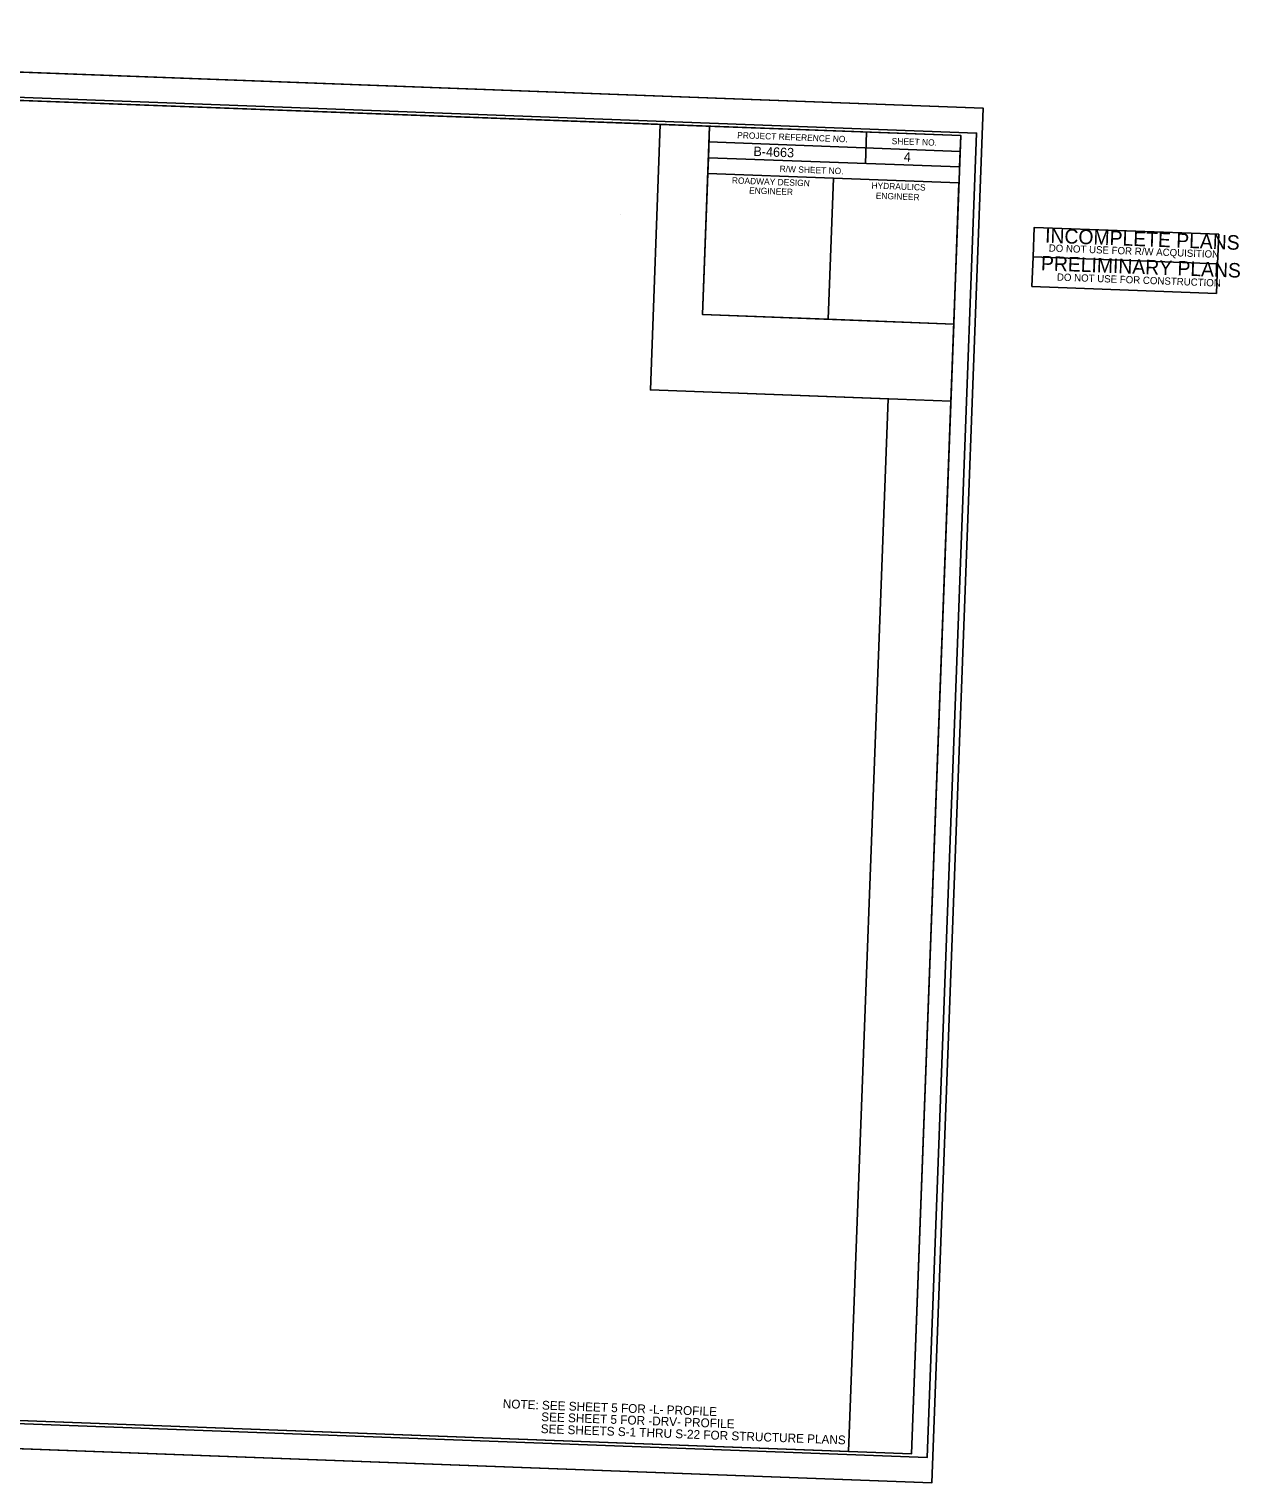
# Model space of a CAD drawing. Extents: x 2170073 to 2172001, y 723518 to 724675.
# Drawn here: x 2171037 to 2172001, y 723518 to 724675 of the extents above; entities that cross this region are included whole.
import ezdxf

# ---------------------------------------------------------------- set-up
doc = ezdxf.new("R2010")
doc.units = 0
for name, color, linetype in [('Prop Dimension Text', 7, 'Continuous'), ('Sheet Clip Boundary CELL', 7, 'Continuous'), ('Sheet Cutting Line CELL', 7, 'Continuous'), ('Sheet Data Field CELL', 7, 'Continuous'), ('Sheet North Arrow Point CELL', 7, 'Continuous'), ('Sheet Plan CELL', 7, 'Continuous'), ('Sheet Plan Layout CELL', 7, 'Continuous'), ('Sheet Plot Border Inside CELL', 7, 'Continuous'), ('Sheet Plot Border Outside CELL', 7, 'Continuous'), ('Sheet Sticker Incomplete CELL', 7, 'Continuous'), ('Sheet Sticker Preliminary CELL', 7, 'Continuous')]:
    doc.layers.add(name, color=color, linetype=linetype)

msp = doc.modelspace()

# ---------------------------------------------------------------- linework, layer by layer
at = {"layer": 'Sheet Clip Boundary CELL'}
msp.add_lwpolyline([(2170290.1, 723595.5), (2171689.1, 723543.2), (2171720.5, 724381.1), (2171531.3, 724388.2), (2171539.2, 724599.5), (2170329.3, 724644.8)], close=True, dxfattribs=at)
at = {"layer": 'Sheet Cutting Line CELL'}
for p, q in [((2171796.2, 724612.4), (2170113.8, 724675.4)), ((2170072.9, 723581.1), (2171755.2, 723518.2))]:
    msp.add_line(p, q, dxfattribs=at)
at = {"layer": 'Sheet North Arrow Point CELL'}
msp.add_line((2171507.7, 724527.7), (2171507.7, 724527.7), dxfattribs=at)
at = {"layer": 'Sheet Plan CELL'}
for p, q in [((2171703.3, 724593.3), (2171702.5, 724568.3)), ((2171577.9, 724585.5), (2171777.8, 724578)), ((2171577.5, 724573), (2171577, 724560.5)), ((2171577.5, 724573), (2171777.4, 724565.6)), ((2171577.5, 724573), (2171777.4, 724565.6)), ((2171677, 724556.8), (2171672.8, 724444.4))]:
    msp.add_line(p, q, dxfattribs=at)
for points in [[(2171778.4, 724590.6), (2170279.4, 724646.7), (2170240.1, 723597.4), (2171739.1, 723541.3)], [(2170240.1, 723597.4), (2170279.3, 724646.6), (2171578.4, 724598.1), (2171572.8, 724448.1), (2171772.7, 724440.6), (2171739.1, 723541.3)], [(2171578.4, 724598.1), (2171778.4, 724590.6), (2171777.4, 724565.6), (2171577.5, 724573)], [(2171577, 724560.5), (2171677, 724556.8), (2171672.8, 724444.4), (2171572.8, 724448.1)], [(2171677, 724556.8), (2171776.9, 724553.1), (2171772.7, 724440.6), (2171672.8, 724444.4)]]:
    msp.add_lwpolyline(points, close=True, dxfattribs=at)
at = {"layer": 'Sheet Plan Layout CELL'}
for points in [[(2170279.3, 724646.6), (2170240.1, 723597.4), (2171739.1, 723541.3), (2171770.4, 724379.2), (2171531.3, 724388.2), (2171539.2, 724599.5)], [(2171531.3, 724388.2), (2171770.4, 724379.2), (2171778.4, 724590.6), (2171539.2, 724599.5)]]:
    msp.add_lwpolyline(points, close=True, dxfattribs=at)
at = {"layer": 'Sheet Plot Border Inside CELL'}
msp.add_lwpolyline([(2170086.6, 723600.6), (2171751.5, 723538.4), (2171790.9, 724592.6), (2170126.1, 724654.9)], close=True, dxfattribs=at)
at = {"layer": 'Sheet Plot Border Outside CELL'}
msp.add_lwpolyline([(2170072.9, 723581.1), (2171755.2, 723518.2), (2171796.2, 724612.4), (2170113.8, 724675.4)], close=True, dxfattribs=at)
at = {"layer": 'Sheet Sticker Incomplete CELL'}
msp.add_lwpolyline([(2171835.9, 724494), (2171836.8, 724517.5), (2171983.7, 724512), (2171982.8, 724488.5)], close=True, dxfattribs=at)
at = {"layer": 'Sheet Sticker Preliminary CELL'}
msp.add_lwpolyline([(2171835, 724470.5), (2171835.9, 724494), (2171982.8, 724488.5), (2171981.9, 724465)], close=True, dxfattribs=at)

# ---------------------------------------------------------------- texts
at = {"layer": 'Prop Dimension Text'}
for s, p in [('NOTE: SEE SHEET 5 FOR -L- PROFILE', (2171413.7, 723577.8)), ('SEE SHEET 5 FOR -DRV- PROFILE', (2171444.3, 723567.4)), ('SEE SHEETS S-1 THRU S-22 FOR STRUCTURE PLANS', (2171443.9, 723557.9))]:
    msp.add_text(s, height=7, rotation=357.8574, dxfattribs=at).set_placement(p)
at = {"layer": 'Sheet Data Field CELL'}
for s, p in [(' B-4663  ', (2171610.4, 724574.5)), (' 4 ', (2171730.1, 724570.1))]:
    msp.add_text(s, height=7.5, rotation=357.8574, dxfattribs=at).set_placement(p)
at = {"layer": 'Sheet Plan CELL'}
for s, p in [('PROJECT REFERENCE NO.', (2171600.3, 724588.5)), ('SHEET NO.', (2171723.3, 724583.8)), ('R/W SHEET NO.', (2171634.1, 724561.7)), ('ROADWAY DESIGN', (2171596.1, 724552.5)), ('ENGINEER', (2171609.8, 724544.5)), ('HYDRAULICS', (2171707.2, 724548.4)), ('ENGINEER', (2171710.6, 724540.3))]:
    msp.add_text(s, height=5, rotation=357.8574, dxfattribs=at).set_placement(p)
at = {"layer": 'Sheet Sticker Incomplete CELL'}
for s, height, p in [('INCOMPLETE PLANS', 11.52, (2171845.3, 724505.4)), ('DO NOT USE FOR R/W ACQUISITION', 5.76, (2171848.3, 724498.3))]:
    msp.add_text(s, height=height, rotation=357.8574, dxfattribs=at).set_placement(p)
at = {"layer": 'Sheet Sticker Preliminary CELL'}
for s, height, p in [('PRELIMINARY PLANS', 11.52, (2171842, 724483.4)), ('DO NOT USE FOR CONSTRUCTION', 5.76, (2171854.8, 724475.2))]:
    msp.add_text(s, height=height, rotation=357.8574, dxfattribs=at).set_placement(p)

doc.saveas('drawing.dxf')
